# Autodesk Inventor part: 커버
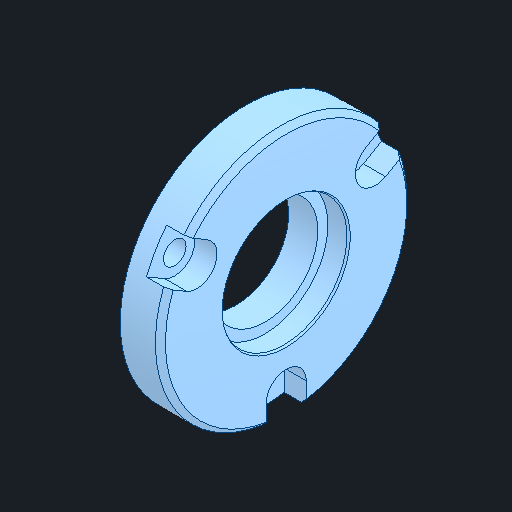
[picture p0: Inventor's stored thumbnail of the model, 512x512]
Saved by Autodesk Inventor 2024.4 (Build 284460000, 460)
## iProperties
Created: 2025-10
Part Number: 커버
Material: 알루미늄 6061
Document SubType Name: Modeling
Designer: user
Density: 2.7 g/cm^3
Appearance: 기본값
Author: jhkim
Sending System: Autodesk Inventor 2026
Preprocessor: ST-DEVELOPER v20.1
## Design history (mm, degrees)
feature "솔리드1"
node "솔리드2"
